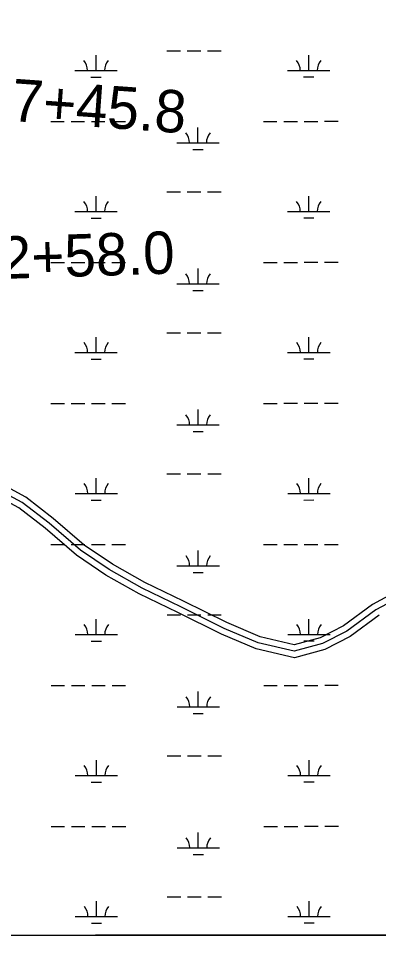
# Model space of a CAD drawing. Extents: x 3279314 to 3317160, y 734079 to 759431.
# Drawn here: x 3294295 to 3295145, y 739456 to 741625 of the extents above; entities that cross this region are included whole.
import ezdxf

# ---------------------------------------------------------------- set-up
doc = ezdxf.new("R2010")
doc.units = 0
for name, color, linetype in [('V-GRID-FRAM', 7, 'Continuous'), ('V-ROAD-CNTR', 7, 'Continuous'), ('V-SITE-VEGE', 7, 'Continuous'), ('V-SURV-IDEN', 7, 'Continuous'), ('V-WETL-SWMP', 7, 'Continuous')]:
    doc.layers.add(name, color=color, linetype=linetype)

msp = doc.modelspace()

# ---------------------------------------------------------------- linework, layer by layer
at = {"layer": 'V-GRID-FRAM'}
msp.add_lwpolyline([(3283455.7, 757641.4), (3314923.7, 757657.4), (3314940.9, 739471.9), (3283457, 739455.9), (3283455.7, 757641.4)], dxfattribs=at)
at = {"layer": 'V-ROAD-CNTR'}
for points in [[(3295204.3, 740264.1), (3295139, 740229.4), (3295070.4, 740178.8), (3295013, 740149.5), (3294946.4, 740131.5), (3294861.1, 740151.5), (3294781.1, 740185.5), (3294678.4, 740236.1), (3294587.1, 740280.1), (3294509.8, 740324.1), (3294441.8, 740370.1), (3294367.8, 740433.4), (3294304.5, 740482.7), (3294213.2, 740531.4), (3294139.2, 740603.4), (3294103, 740624.1)], [(3295204.3, 740264.1), (3295139, 740229.4), (3295070.4, 740178.8), (3295013, 740149.5), (3294946.4, 740131.5), (3294861.1, 740151.5), (3294781.1, 740185.5), (3294678.4, 740236.1), (3294587.1, 740280.1), (3294509.8, 740324.1), (3294441.8, 740370.1), (3294367.8, 740433.4), (3294304.5, 740482.7), (3294213.2, 740531.4), (3294139.2, 740603.4), (3294103, 740624.1)], [(3295197.9, 740277.7), (3295131, 740242.2), (3295062.4, 740191.6), (3295007.6, 740163.5), (3294946.1, 740146.9), (3294865.7, 740165.8), (3294787.3, 740199.1), (3294685, 740249.6), (3294594.1, 740293.4), (3294517.7, 740336.9), (3294450.9, 740382), (3294377.3, 740445), (3294312.7, 740495.4), (3294222.1, 740543.6), (3294148.3, 740615.5), (3294110.4, 740637.2)], [(3295147, 740216.7), (3295078.3, 740166), (3295018.5, 740135.4), (3294946.6, 740116), (3294856.4, 740137.2), (3294774.8, 740171.8), (3294671.9, 740222.6), (3294580.1, 740266.8), (3294501.9, 740311.4), (3294432.7, 740358.1), (3294358.3, 740421.8), (3294296.3, 740470.1), (3294204.2, 740519.2), (3294130.1, 740591.3), (3294095.5, 740611.1)]]:
    msp.add_lwpolyline(points, dxfattribs=at)
at = {"layer": 'V-SITE-VEGE'}
msp.add_line((3293934.4, 739461.2), (3295785, 739462.2), dxfattribs=at)
at = {"layer": 'V-WETL-SWMP'}
for p, q in [((3294478.5, 741501.6), (3294478.5, 741537.6)), ((3294645.5, 741548.2), (3294677.5, 741548.2)), ((3294693.5, 741548.2), (3294725.5, 741548.2)), ((3294741.5, 741548.2), (3294773.5, 741548.2)), ((3294980.4, 741501.9), (3294980.4, 741537.9)), ((3294428.5, 741501.6), (3294528.5, 741501.7)), ((3294930.4, 741501.9), (3295030.4, 741501.9)), ((3294466.5, 741486.2), (3294490.5, 741486.2)), ((3294968.4, 741486.5), (3294992.4, 741486.5)), ((3294371.7, 741381.5), (3294403.7, 741381.5)), ((3294419.7, 741381.5), (3294451.7, 741381.6)), ((3294467.7, 741381.6), (3294499.7, 741381.6)), ((3294515.7, 741381.6), (3294547.7, 741381.6)), ((3294873.6, 741381.8), (3294905.6, 741381.8)), ((3294921.6, 741381.8), (3294953.6, 741381.8)), ((3294969.6, 741381.8), (3295001.6, 741381.8)), ((3295017.6, 741381.9), (3295049.6, 741381.9)), ((3294719, 741331), (3294719, 741367)), ((3294669, 741330.9), (3294769, 741331)), ((3294707.1, 741315.5), (3294731.1, 741315.5)), ((3294645.7, 741215.5), (3294677.7, 741215.5)), ((3294693.7, 741215.5), (3294725.7, 741215.5)), ((3294741.7, 741215.5), (3294773.7, 741215.6)), ((3294478.7, 741169), (3294478.6, 741205)), ((3294980.6, 741169.2), (3294980.5, 741205.2)), ((3294428.7, 741168.9), (3294528.7, 741169)), ((3294930.6, 741169.2), (3295030.6, 741169.3)), ((3294466.7, 741153.5), (3294490.7, 741153.5)), ((3294968.6, 741153.8), (3294992.6, 741153.8)), ((3294371.9, 741048.8), (3294403.9, 741048.9)), ((3294419.9, 741048.9), (3294451.9, 741048.9)), ((3294467.9, 741048.9), (3294499.9, 741048.9)), ((3294515.9, 741048.9), (3294547.9, 741048.9)), ((3294719.2, 740998.3), (3294719.2, 741034.3)), ((3294873.8, 741049.1), (3294905.8, 741049.1)), ((3294921.8, 741049.1), (3294953.8, 741049.1)), ((3294969.8, 741049.2), (3295001.8, 741049.2)), ((3295017.8, 741049.2), (3295049.8, 741049.2)), ((3294669.2, 740998.3), (3294769.2, 740998.3)), ((3294707.2, 740982.8), (3294731.2, 740982.9)), ((3294645.9, 740882.8), (3294677.9, 740882.8)), ((3294693.9, 740882.8), (3294725.9, 740882.9)), ((3294741.9, 740882.9), (3294773.9, 740882.9)), ((3294478.8, 740836.3), (3294478.8, 740872.3)), ((3294980.7, 740836.6), (3294980.7, 740872.6)), ((3294428.8, 740836.3), (3294528.8, 740836.3)), ((3294466.8, 740820.9), (3294490.8, 740820.9)), ((3294930.7, 740836.5), (3295030.7, 740836.6)), ((3294968.7, 740821.1), (3294992.7, 740821.1)), ((3294372, 740716.2), (3294404, 740716.2)), ((3294420, 740716.2), (3294452, 740716.2)), ((3294468, 740716.2), (3294500, 740716.2)), ((3294516, 740716.2), (3294548, 740716.3)), ((3294874, 740716.4), (3294906, 740716.4)), ((3294922, 740716.5), (3294954, 740716.5)), ((3294970, 740716.5), (3295002, 740716.5)), ((3295018, 740716.5), (3295050, 740716.5)), ((3294719.4, 740665.6), (3294719.4, 740701.6)), ((3294669.4, 740665.6), (3294769.4, 740665.6)), ((3294707.4, 740650.2), (3294731.4, 740650.2)), ((3294479, 740503.6), (3294479, 740539.6)), ((3294646, 740550.1), (3294678, 740550.2)), ((3294694, 740550.2), (3294726, 740550.2)), ((3294742, 740550.2), (3294774, 740550.2)), ((3294980.9, 740503.9), (3294980.9, 740539.9)), ((3294429, 740503.6), (3294529, 740503.7)), ((3294930.9, 740503.9), (3295030.9, 740503.9)), ((3294467, 740488.2), (3294491, 740488.2)), ((3294968.9, 740488.4), (3294992.9, 740488.5)), ((3294372.2, 740383.5), (3294404.2, 740383.5)), ((3294420.2, 740383.5), (3294452.2, 740383.5)), ((3294468.2, 740383.5), (3294500.2, 740383.6)), ((3294516.2, 740383.6), (3294548.2, 740383.6)), ((3294874.1, 740383.8), (3294906.1, 740383.8)), ((3294922.1, 740383.8), (3294954.1, 740383.8)), ((3294970.1, 740383.8), (3295002.1, 740383.8)), ((3295018.1, 740383.8), (3295050.1, 740383.8)), ((3294719.6, 740332.9), (3294719.5, 740368.9)), ((3294669.6, 740332.9), (3294769.6, 740333)), ((3294707.6, 740317.5), (3294731.6, 740317.5)), ((3294646.2, 740217.5), (3294678.2, 740217.5)), ((3294694.2, 740217.5), (3294726.2, 740217.5)), ((3294742.2, 740217.5), (3294774.2, 740217.5)), ((3294479.2, 740171), (3294479.1, 740207)), ((3294981.1, 740171.2), (3294981.1, 740207.2)), ((3294429.2, 740170.9), (3294529.2, 740171)), ((3294931.1, 740171.2), (3295031.1, 740171.2)), ((3294467.2, 740155.5), (3294491.2, 740155.5)), ((3294969.1, 740155.8), (3294993.1, 740155.8)), ((3294372.4, 740050.8), (3294404.4, 740050.8)), ((3294420.4, 740050.9), (3294452.4, 740050.9)), ((3294468.4, 740050.9), (3294500.4, 740050.9)), ((3294516.4, 740050.9), (3294548.4, 740050.9)), ((3294719.7, 740000.3), (3294719.7, 740036.3)), ((3294874.3, 740051.1), (3294906.3, 740051.1)), ((3294922.3, 740051.1), (3294954.3, 740051.1)), ((3294970.3, 740051.1), (3295002.3, 740051.1)), ((3295018.3, 740051.2), (3295050.3, 740051.2)), ((3294669.7, 740000.2), (3294769.7, 740000.3)), ((3294707.7, 739984.8), (3294731.7, 739984.8)), ((3294646.4, 739884.8), (3294678.4, 739884.8)), ((3294694.4, 739884.8), (3294726.4, 739884.8)), ((3294742.4, 739884.8), (3294774.4, 739884.9)), ((3294479.3, 739838.3), (3294479.3, 739874.3)), ((3294981.2, 739838.5), (3294981.2, 739874.5)), ((3294429.3, 739838.3), (3294529.3, 739838.3)), ((3294467.3, 739822.8), (3294491.3, 739822.9)), ((3294931.2, 739838.5), (3295031.2, 739838.6)), ((3294969.2, 739823.1), (3294993.2, 739823.1)), ((3294372.5, 739718.2), (3294404.5, 739718.2)), ((3294420.5, 739718.2), (3294452.5, 739718.2)), ((3294468.5, 739718.2), (3294500.5, 739718.2)), ((3294516.5, 739718.2), (3294548.5, 739718.2)), ((3294874.5, 739718.4), (3294906.5, 739718.4)), ((3294922.5, 739718.4), (3294954.5, 739718.4)), ((3294970.5, 739718.5), (3295002.5, 739718.5)), ((3295018.5, 739718.5), (3295050.5, 739718.5)), ((3294719.9, 739667.6), (3294719.9, 739703.6)), ((3294669.9, 739667.6), (3294769.9, 739667.6)), ((3294707.9, 739652.2), (3294731.9, 739652.2)), ((3294479.5, 739505.6), (3294479.5, 739541.6)), ((3294646.5, 739552.1), (3294678.5, 739552.1)), ((3294694.5, 739552.1), (3294726.5, 739552.2)), ((3294742.5, 739552.2), (3294774.5, 739552.2)), ((3294981.4, 739505.9), (3294981.4, 739541.9)), ((3294429.5, 739505.6), (3294529.5, 739505.6)), ((3294931.4, 739505.8), (3295031.4, 739505.9)), ((3294467.5, 739490.2), (3294491.5, 739490.2)), ((3294969.4, 739490.4), (3294993.4, 739490.4)), ((3293934.4, 739461.2), (3296814.2, 739462.7)), ((3293934.4, 739461.2), (3296814.2, 739462.7))]:
    msp.add_line(p, q, dxfattribs=at)
for centre, start, end in [((3294423.2, 741502.1), 359.2573, 40.801), ((3294533.7, 741502.2), 139.2573, 180.801), ((3294925.2, 741502.4), 359.2573, 40.801), ((3295035.6, 741502.4), 139.2573, 180.801), ((3294663.8, 741331.4), 359.2573, 40.801), ((3294774.3, 741331.5), 139.2573, 180.801), ((3294423.4, 741169.4), 359.2573, 40.801), ((3294533.9, 741169.5), 139.2573, 180.801), ((3294925.3, 741169.7), 359.2573, 40.801), ((3295035.8, 741169.7), 139.2573, 180.801), ((3294664, 740998.7), 359.2573, 40.801), ((3294774.5, 740998.8), 139.2573, 180.801), ((3294423.6, 740836.7), 359.2573, 40.801), ((3294534.1, 740836.8), 139.2573, 180.801), ((3294925.5, 740837), 359.2573, 40.801), ((3295036, 740837.1), 139.2573, 180.801), ((3294664.1, 740666.1), 359.2573, 40.801), ((3294774.6, 740666.1), 139.2573, 180.801), ((3294423.8, 740504.1), 359.2573, 40.801), ((3294534.2, 740504.1), 139.2573, 180.801), ((3294925.7, 740504.3), 359.2573, 40.801), ((3295036.1, 740504.4), 139.2573, 180.801), ((3294664.3, 740333.4), 359.2573, 40.801), ((3294774.8, 740333.4), 139.2573, 180.801), ((3294423.9, 740171.4), 359.2573, 40.801), ((3294534.4, 740171.5), 139.2573, 180.801), ((3294925.8, 740171.7), 359.2573, 40.801), ((3295036.3, 740171.7), 139.2573, 180.801), ((3294664.5, 740000.7), 359.2573, 40.801), ((3294775, 740000.8), 139.2573, 180.801), ((3294424.1, 739838.7), 359.2573, 40.801), ((3294534.6, 739838.8), 139.2573, 180.801), ((3294926, 739839), 359.2573, 40.801), ((3295036.5, 739839), 139.2573, 180.801), ((3294664.6, 739668), 359.2573, 40.801), ((3294775.1, 739668.1), 139.2573, 180.801), ((3294424.3, 739506), 359.2573, 40.801), ((3294534.7, 739506.1), 139.2573, 180.801), ((3294926.2, 739506.3), 359.2573, 40.801), ((3295036.6, 739506.4), 139.2573, 180.801)]:
    msp.add_arc(centre, 35.2, start, end, dxfattribs=at)

# ---------------------------------------------------------------- texts
at = {"layer": 'V-SURV-IDEN'}
for s, rotation, p in [('3127+45.8', 355.8981, (3294053.9, 741398.8)), ('3132+58.0', 1.8389, (3294029.9, 741002.6))]:
    msp.add_text(s, height=100, rotation=rotation, dxfattribs=at).set_placement(p)

doc.saveas('drawing.dxf')
